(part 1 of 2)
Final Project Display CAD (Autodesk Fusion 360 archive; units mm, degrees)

design "Display Mechanism" references "STEP214 DIGITAL SERVO ASSEMBLY", "M4x2.2mm Hex Nut"
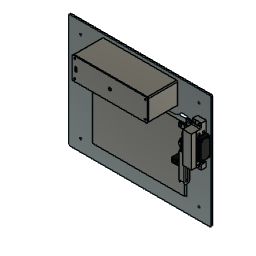
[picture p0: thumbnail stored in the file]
parameter "CaseWidth" = 190.24
parameter "CaseHeight" = 131.19
parameter "CaseThickness" = 9.525 (= "( 0.125 * 3 ) * 1 in")
parameter "FrameOffsetFromCase" = 2 comment "each side"
parameter "FrameSize" = 50 comment "width of each side"
parameter "HoleCenterFromTop" = 10 comment "pin hole in case distance to the center of the hole from the top of the csae"
parameter "PinDiameter" = 5
parameter "PinTolerance" = 1
parameter "PinDistanceIntoCase" = 10
parameter "PinEndTolerance" = 1 comment "distance between the end of the pin and the end of the pinhole in the case"
parameter "ServoArmFitTolerance" = 0.25
parameter "CaseAttachmentCircleTolerance" = 0.3
parameter "HexNutOffset" = -0.435 (= "2.54 mm - 3.475 mm + 0.5 mm") comment "hex nut hole offset in case attachment"
parameter "CaseAttachmentTolerance" = 0.3 comment "each side of the u-shape's offset from the case"
parameter "ServoMountSidesOffset" = 0.5
parameter "ServoMountScrewholePlaneOffset" = 1 comment "the plane perpendicular to the screws' offset from the plane with the screws"
parameter "PinHoleTolerance" = 0.2 comment "Tolerance on each side of the cylindrical pin"
parameter "HingeFrameCaseTolerance" = 0.2
sketch "Sketch1" plane through (0, 0, 0) normal (0, 1, 0) x axis (1, 0, 0)
  line L1 (-95.12, -65.595) -> (95.12, -65.595)
  line L2 (-95.12, 65.595) -> (-95.12, -65.595)
  line L3 (95.12, 65.595) -> (-95.12, 65.595)
  line L4 (95.12, -65.595) -> (95.12, 65.595)
  line L5 (-95.12, 65.595) -> (95.12, -65.595)
  line L6 (95.12, 65.595) -> (-95.12, -65.595)
  point P6 (0, 0)
  point P1 (0, 0)
  point P2 (95.12, -65.595)
  point P5 (95.12, 65.595)
  point P4 (-95.12, 65.595)
  horizontal L1
  perpendicular L1 L2
  parallel L1 L3
  parallel L2 L4
  coincident L5 P6
  coincident L6 P6
  coincident P1 P6
  dimension "d3" distance P2 P5 = 131.19 (= "CaseHeight")
  dimension "d4" distance P4 P5 = 190.24 (= "CaseWidth")
extrude "Extrude1" new body sketch "Sketch1" profile of L1 L2 L3 L4 along normal blind 9.525 (= "CaseThickness")
sketch "Sketch2" plane through (0, 0, 0) normal (0, -1, 0) x axis (1, 0, 0)
  line L1 (95.12, -65.595) -> (-95.12, -65.595)
  line L2 (95.12, 65.595) -> (95.12, -65.595)
  line L3 (-95.12, 65.595) -> (95.12, 65.595)
  line L4 (-95.12, -65.595) -> (-95.12, 65.595)
  line L5 (97.12, -67.595) -> (-97.12, -67.595)
  line L6 (97.12, 67.595) -> (97.12, -67.595)
  line L7 (-97.12, 67.595) -> (97.12, 67.595)
  line L8 (-97.12, -67.595) -> (-97.12, 67.595)
  line L9 (147.12, -117.595) -> (-147.12, -117.595)
  line L10 (147.12, 117.595) -> (147.12, -117.595)
  line L11 (-147.12, 117.595) -> (147.12, 117.595)
  line L12 (-147.12, -117.595) -> (-147.12, 117.595)
  dimension "d10" = 2 (= "FrameOffsetFromCase")
  dimension "d11" = 52 (= "FrameOffsetFromCase + FrameSize")
extrude "Extrude2" new body sketch "Sketch2" profile of L6 L5 L7 L8 L10 L9 L11 L12 no distance stored bodies "Frame"
sphere_primitive "SpherePrimitive1" Diameter 30
move_face "MoveFace1"
move "Move1"
work_plane "WorkPlane1" AlongDistance 8
split "Split1"
remove_body "RemoveBody1"
mirror "Mirror1" mirrorStitchTolerance 0.1
mirror "Mirror2" mirrorStitchTolerance 0.1
combine "Combine1"
sketch "Sketch4" plane through (95.12, 0, 0) normal (1, 0, 0) x axis (0, 1, 0)
  line L1 (0, -65.595) -> (0, 65.595)
  line L2 (9.525, -65.595) -> (0, -65.595)
  line L3 (9.525, 65.595) -> (9.525, -65.595)
  line L4 (0, 65.595) -> (9.525, 65.595)
  line L5 (4.7625, 55.595) -> (4.7625, 65.595)
  circle C1 centre (4.7625, 55.595) radius 3
  point P6 (4.7625, 65.595)
  point P7 (4.7625, 55.595)
  point P8 (4.7625, 55.595)
  midpoint L4 P6
  perpendicular L4 L5
  coincident P7 P8
  dimension "d21" distance P6 P7 = 10
  dimension "d24" diameter C1 = 6 (= "PinDiameter + PinTolerance")
extrude "Extrude3" cut sketch "Sketch4" profile of C1 no distance stored
sketch "Sketch5" plane through (97.12, 0, 0) normal (-1, 0, 0) x axis (0, -1, 0)
  line L1 (0, 67.595) -> (0, -67.595)
  line L2 (-9.525, 67.595) -> (0, 67.595)
  line L3 (-9.525, -67.595) -> (-9.525, 67.595)
  line L4 (0, -67.595) -> (-9.525, -67.595)
  circle C1 centre (-4.7625, 55.595) radius 3
  circle C2 centre (-4.7625, 55.595) radius 2.5
  concentric C1 C2
  dimension "d29" diameter C2 = 5 (= "PinDiameter")
extrude "Extrude4" add sketch "Sketch5" profile of C2 along normal blind 12 (= "FrameOffsetFromCase + PinDistanceIntoCase")
fillet "Fillet1" radius 3
mirror "Mirror3" mirrorStitchTolerance 0.1
sketch "Sketch6" plane through (0, 0, 0) normal (0, -1, 0) x axis (1, 0, 0)
  line L1 (-97.12, 52.8439) -> (-97.12, -67.595)
  line L2 (97.12, 67.595) -> (-97.12, 67.595)
  line L3 (97.12, 58.3461) -> (97.12, 67.595)
  curve K1 (97.12, 58.3461) -> (97.12, 52.8439)
  line L4 (97.12, -67.595) -> (97.12, 52.8439)
  line L5 (-97.12, -67.595) -> (97.12, -67.595)
  line L6 (-147.12, -117.595) -> (-147.12, 117.595)
  line L7 (147.12, -117.595) -> (-147.12, -117.595)
  line L8 (147.12, 117.595) -> (147.12, -117.595)
  line L9 (-147.12, 117.595) -> (147.12, 117.595)
  line L10 (140.0818, 50) -> (110, 50)
  line L11 (140.0818, 32.2031) -> (140.0818, 50)
  line L12 (110, 32.2031) -> (140.0818, 32.2031)
  line L13 (110, 50) -> (110, 32.2031)
  curve K2 (-97.12, 52.8439) -> (-97.12, 58.3461)
  line L14 (-97.12, 67.595) -> (-97.12, 58.3461)
  horizontal L10
  vertical L11
  horizontal L12
  vertical L13
extrude "Extrude5" new body sketch "Sketch6" profile of L10 L11 L12 L13 along normal blind 30 bodies "Servo"
sketch "Sketch7" plane through (0, 0, 0) normal (0, -1, 0) x axis (1, 0, 0)
  line L1 (95.12, -65.595) -> (-95.12, -65.595)
  line L2 (95.12, 65.595) -> (95.12, -65.595)
  line L3 (-95.12, 65.595) -> (95.12, 65.595)
  line L4 (-95.12, -65.595) -> (-95.12, 65.595)
  line L5 (89, 7.3258) -> (95.12, 7.3258)
  line L6 (89, 1) -> (89, 7.3258)
  line L7 (95.12, 1) -> (89, 1)
  line L8 (95.12, 7.3258) -> (95.12, 1)
  point P6 (95.12, 7.3258)
  horizontal L5
  vertical L6
  horizontal L7
  vertical L8
  coincident L2 P6
sketch "Sketch8" plane through (110, 0, 0) normal (-1, 0, 0) x axis (0, -1, 0)
  line L1 (0, 32.2031) -> (0, 50)
  line L2 (30, 32.2031) -> (0, 32.2031)
  line L3 (30, 50) -> (30, 32.2031)
  line L4 (0, 50) -> (30, 50)
  line L5 (0, 41.1016) -> (30, 41.1016)
  circle C1 centre (5.9888, 41.1016) radius 2.8985
  point P6 (30, 41.1016)
  point P7 (0, 41.1016)
  point P8 (5.9888, 41.1016)
  midpoint L3 P6
  midpoint L1 P7
  coincident L5 P8
extrude "Extrude6" add sketch "Sketch8" profile of C1 along normal blind 5
extrude "Extrude7" add sketch "Sketch7" profile of L2 L5 L6 L7 L8 along normal blind 20
sketch "Sketch9" plane through (95.12, 0, 0) normal (1, 0, 0) x axis (0, 1, 0)
  line L1 (0, -65.595) -> (0, 1)
  line L2 (9.525, -65.595) -> (0, -65.595)
  line L3 (9.525, 65.595) -> (9.525, -65.595)
  line L4 (0, 65.595) -> (9.525, 65.595)
  line L5 (0, 7.3258) -> (0, 65.595)
  line L6 (-20, 7.3258) -> (0, 7.3258)
  line L7 (-20, 1) -> (-20, 7.3258)
  line L8 (0, 1) -> (-20, 1)
  line L9 (-20, 7.3258) -> (0, 7.3258)
  line L10 (-20, 7.3258) -> (-20, 1)
  line L11 (-20, 1) -> (0, 1)
  line L12 (-1.5907, 4.1629) -> (-20, 4.1629)
  circle C1 centre (4.7625, 55.595) radius 3
  circle C2 centre (-7.1563, 4.1629) radius 2
  point P16 (-20, 4.1629)
  point P11 (-7.1563, 4.1629)
  midpoint L10 P16
  coincident P11 L12
  horizontal L12
extrude "Extrude8" add sketch "Sketch9" profile of C2 along normal blind 14
fillet "Fillet2" radius 5
sketch "Sketch10" plane through (105, 0, 0) normal (-1, 0, 0) x axis (0, -1, 0)
  line L1 (5.1563, 41) -> (5.1563, 4.1629)
  line L2 (9.1563, 41) -> (5.1563, 41)
  line L3 (9.1563, 4.1629) -> (9.1563, 41)
  line L4 (5.1563, -6.9539) -> (5.1563, 4.1629)
  line L5 (9.1563, -6.9539) -> (9.1563, 4.1629)
  line L6 (10.1563, -6.9539) -> (10.1563, 4.1629)
  line L7 (4.1563, -6.9539) -> (4.1563, 4.1629)
  line L8 (4.1563, 42) -> (4.1563, 4.1629)
  line L9 (10.1563, 42) -> (4.1563, 42)
  line L10 (10.1563, 4.1629) -> (10.1563, 42)
  circle C1 centre (5.9888, 41.1016) radius 2.8985
  circle C2 centre (7.1563, 4.1629) radius 2
  arc A1 centre (7.1563, 4.1629) radius 2 clockwise from (9.1563, 4.1629) to (5.1563, 4.1629)
  arc A2 centre (7.1563, -6.9539) radius 2 clockwise from (9.1563, -6.9539) to (5.1563, -6.9539)
  arc A3 centre (7.1563, -6.9539) radius 3 clockwise from (10.1563, -6.9539) to (4.1563, -6.9539)
  point P4 (5.1563, 4.1629)
  point P7 (9.1563, 4.1629)
  coincident C2 P4
  tangent C2 L1
  vertical L1
  perpendicular L1 L2
  coincident C2 P7
  tangent C2 L3
  perpendicular L2 L3
  tangent L3 A1
  tangent C2 L4
  tangent A1 L5
  tangent L5 A2
  tangent L4 A2
  dimension "d49" = -1
extrude "Extrude9" new body sketch "Sketch10" profile of C1 L1 L2 L3 L4 L5 A2 L6 L10 L7 A3 L8 L9 along normal blind 1
sketch "Sketch11" plane through (104, 0, 0) normal (-1, 0, 0) x axis (0, -1, 0)
  line L1 (5.1563, 41) -> (5.1563, -6.9539)
  line L2 (9.1563, 41) -> (5.1563, 41)
  line L3 (9.1563, -6.9539) -> (9.1563, 41)
  line L4 (4.1563, -6.9539) -> (4.1563, 42)
  line L5 (10.1563, 42) -> (10.1563, -6.9539)
  line L6 (4.1563, 42) -> (10.1563, 42)
  line L7 (9.1563, 33) -> (5.1563, 33)
  arc A1 centre (7.1563, -6.9539) radius 2 clockwise from (9.1563, -6.9539) to (5.1563, -6.9539)
  arc A2 centre (7.1563, -6.9539) radius 3 clockwise from (10.1563, -6.9539) to (4.1563, -6.9539)
  circle C1 centre (7.1563, 38.8292) radius 1.5
  circle C2 centre (7.1563, 34.8292) radius 1.5
  point P13 (5.1563, 33)
  point P14 (9.1563, 33)
  point P11 (7.1563, 38.8292)
  point P12 (7.1563, 34.8292)
  point P3 (5.1563, 41)
  point P4 (9.1563, 41)
  coincident L1 P13
  coincident L3 P14
  perpendicular L3 L7
  dimension "d50" diameter C1 = 3
  dimension "d51" diameter C2 = 3
  dimension "d52" distance P11 P12 = 4
  dimension "d198" distance P3 P4 = 4
  dimension "d199" distance L3 P11 = 2 (= "d198 / 2")
  dimension "d200" distance L3 P12 = 2 (= "d199")
extrude "Extrude10" new body sketch "Sketch11" profile of L1 L2 L3 C1 C2 L7 against normal blind 1
combine "Combine2"
extrude "Extrude11" new body of existing geometry blind 4
combine "Combine3"
component_from_bodies "Body->Comp1"
component_insert "Component Insert1"
move "Move1"
extrude "Extrude1" add of existing geometry blind 4
extrude "Extrude2" add of existing geometry blind 3
extrude "Extrude3" add of existing geometry blind 3
offset_faces "OffsetFaces1" distance 3
extrude "Extrude4" add of existing geometry blind 5
extrude "Extrude5" add of existing geometry blind 5
combine "Combine1" bodies "Servo Arm Attachment (1)", "Servo Arm Attachment (2)", "Servo Arm Attachment (3)", "Servo Arm Attachment (4)", "Servo Arm Attachment (5)", "Servo Arm Attachment (6)", "Servo Arm Attachment (7)", "Servo Arm Attachment (8)"
offset_faces "OffsetFaces2"
sketch "Sketch1" plane through (0, 0, 27.5) normal (0, 0, 1) x axis (-1, 0, 0)
  line L1 (-100, 13.6) -> (-100.45, 14.05)
  line L2 (-100, 16.0063) -> (-100, 13.6)
  line L3 (-110, 16.0063) -> (-100, 16.0063)
  line L4 (-110, 4.0063) -> (-110, 16.0063)
  line L5 (-100, 4.0063) -> (-110, 4.0063)
  line L6 (-100, 6.4) -> (-100, 4.0063)
  line L7 (-100.45, 5.95) -> (-100, 6.4)
  line L8 (-103.9036, 5.95) -> (-100.45, 5.95)
  line L9 (-104.25, 6.2964) -> (-103.9036, 5.95)
  line L10 (-104.25, 13.7036) -> (-104.25, 6.2964)
  line L11 (-103.9036, 14.05) -> (-104.25, 13.7036)
  line L12 (-100.45, 14.05) -> (-103.9036, 14.05)
  line L13 (-100, 14.05) -> (-100.45, 14.05)
  point P2 (-100.45, 14.05)
  point P14 (-100.45, 14.05)
  point P15 (-100, 14.05)
  coincident P2 P14
  coincident L2 P15
  perpendicular L2 L13
sweep "Sweep1" sketch "Sketch1" TwistAngle 0 TaperAngle 0
extrude "Extrude12" cut of existing geometry blind -2.833
sketch "Sketch13" plane through (0, 0, 7.3258) normal (0, 0, 1) x axis (-1, 0, 0)
  line L1 (-95.12, 17.167) -> (-89, 17.167)
  line L2 (-95.12, 13.401) -> (-95.12, 17.167)
  curve K1 (-95.12, 13.401) -> (-95.12, 0.9116)
  line L3 (-95.12, 0) -> (-95.12, 0.9116)
  line L4 (-89, 0) -> (-95.12, 0)
  line L5 (-89, 17.167) -> (-89, 0)
  line L6 (-112, 0) -> (-95.12, 0)
  line L7 (-112, 18) -> (-112, 0)
  line L8 (-95.12, 18) -> (-112, 18)
  line L9 (-95.12, 0) -> (-95.12, 18)
  point P6 (-95.12, 0)
  point P8 (-95.12, 0)
  horizontal L6
  vertical L7
  horizontal L8
  vertical L9
  coincident P6 P8
extrude "Extrude13" cut sketch "Sketch13" profile of L2 K1 L3 L6 L7 L8 L9 against normal blind 6.326
fillet "Fillet3" radius 2
sketch "Sketch14" plane through (95.12, 0, 0) normal (1, 0, 0) x axis (0, 1, 0)
  line L1 (0, -65.595) -> (0, -1)
  line L2 (9.525, -65.595) -> (0, -65.595)
  line L3 (9.525, 65.595) -> (9.525, -65.595)
  line L4 (0, 65.595) -> (9.525, 65.595)
  line L5 (0, 9.3258) -> (0, 65.595)
  line L6 (-17.167, 7.3258) -> (-2, 7.3258)
  line L7 (-17.167, 1) -> (-17.167, 7.3258)
  line L8 (-2, 1) -> (-17.167, 1)
  line L9 (-12.0063, 9.5) -> (-12.0063, -25.4539)
  line L10 (-8.0063, -25.4539) -> (-8.0063, 9.5)
  line L11 (-8.0063, 9.5) -> (-12.0063, 9.5)
  line L12 (-10.0063, 1.6266) -> (-10.0063, 9.5)
  line L13 (-12.3112, 1) -> (-12.3112, 7.3258)
  line L14 (-9.7419, 4.1629) -> (-12.3112, 4.1629)
  arc A1 centre (-2, 9.3258) radius 2 clockwise from (0, 9.3258) to (-2, 7.3258)
  arc A2 centre (-2, -1) radius 2 clockwise from (-2, 1) to (0, -1)
  circle C1 centre (4.7625, 55.595) radius 3
  circle C2 centre (-11.0265, 4.1629) radius 3.0202
  circle C3 centre (-11.0265, 4.1629) radius 2.7202
  point P19 (-10.0063, 9.5)
  point P21 (-12.3112, 7.3258)
  point P22 (-12.3112, 1)
  point P23 (-12.3112, 4.1629)
  point P25 (-11.0265, 4.1629)
  midpoint L11 P19
  perpendicular L11 L12
  coincident L6 P21
  coincident L8 P22
  perpendicular L8 L13
  midpoint L13 P23
  perpendicular L12 L14
  midpoint L14 P25
  tangent L10 C2
extrude "Extrude14" add sketch "Sketch14" profile of C3 along normal blind 14.88
extrude "Extrude15" add of existing geometry blind 5
split "Split2" bodies "Case Attachment"
position "Position1"
sketch "Sketch15" plane through (0, 9.525, 0) normal (0, 1, 0) x axis (-1, 0, 0)
  line L1 (95.12, -65.595) -> (-95.12, -65.595)
  line L2 (95.12, 65.595) -> (95.12, -65.595)
  line L3 (-95.12, 65.595) -> (95.12, 65.595)
  line L4 (-95.12, -65.595) -> (-95.12, 65.595)
  line L5 (-87, -1) -> (-87, 9.3258)
  line L6 (-87, 9.3258) -> (-95.12, 9.3258)
  line L7 (-95.12, -1) -> (-87, -1)
extrude "Extrude16" add sketch "Sketch15" profile of L4 L5 L6 L7 along normal blind 5
sketch "Sketch16" plane through (95.12, 0, 0) normal (1, 0, 0) x axis (0, 1, 0)
  line L1 (0, -65.595) -> (0, 65.595)
  line L2 (9.525, -65.595) -> (0, -65.595)
  line L3 (9.525, -1) -> (9.525, -65.595)
  line L4 (14.525, -1) -> (9.525, -1)
  line L5 (14.525, 9.3258) -> (14.525, -1)
  line L6 (9.525, 9.3258) -> (14.525, 9.3258)
  line L7 (9.525, 65.595) -> (9.525, 9.3258)
  line L8 (0, 65.595) -> (9.525, 65.595)
  line L9 (0, 9.3258) -> (14.525, 9.3258)
  line L10 (0, -1) -> (14.525, -1)
  circle C1 centre (4.7625, 55.595) radius 3
  point P8 (14.525, 9.3258)
  point P11 (14.525, 9.3258)
  point P12 (0, 9.3258)
  point P7 (14.525, -1)
  point P13 (14.525, -1)
  point P14 (0, -1)
  coincident P8 P11
  coincident L1 P12
  perpendicular L1 L9
  coincident P7 P13
  coincident L1 P14
  perpendicular L1 L10
extrude "Extrude17" add sketch "Sketch16" profile of L1 L4 L5 L6 L9 L10 along normal blind 1.5 bodies "Case Attachment"
split "Split3" bodies "Case Attachment"
split "Split4" bodies "Case (2)"
work_plane "WorkPlane2" AlongDistance 0
split "Split5" bodies "Case (3)"
work_plane "WorkPlane3" RotateAngle 90
split "Split6" bodies "Case (2) (1)"
move "Move2"
combine "Combine4" bodies "Case (2)"
extrude "Extrude18" new body of existing geometry blind 2
extrude "Extrude19" new body of existing geometry blind 2
combine "Combine5" bodies "Case (2) (1)", "Case (3)"
fillet "Fillet5" radius 3
sketch "Sketch17" plane through (0, 14.525, 0) normal (0, 1, 0) x axis (-1, 0, 0)
  line L1 (-87, -1) -> (-96.62, -1)
  line L2 (-87, 9.3258) -> (-87, -1)
  line L3 (-96.62, 9.3258) -> (-87, 9.3258)
  line L4 (-96.62, -1) -> (-96.62, 9.3258)
  line L5 (-87, -1) -> (-96.62, 9.3258)
  line L6 (-96.62, -1) -> (-87, 9.3258)
  circle C1 centre (-91.81, 4.1629) radius 2
  point P3 (-87, -1)
  point P6 (-87, -1)
  point P4 (-87, 9.3258)
  point P7 (-87, 9.3258)
  point P8 (-96.62, -1)
  point P9 (-91.81, 4.1629)
  point P5 (-96.62, 9.3258)
  point P10 (-96.62, 9.3258)
  coincident P3 P6
  coincident P4 P7
  coincident L1 P8
  midpoint L6 P9
  coincident P5 P10
  dimension "d102" diameter C1 = 4
extrude "Extrude20" cut sketch "Sketch17" profile of C1 against normal blind 31.692
component_from_bodies "Body->Comp2"
sketch "Sketch1" plane through (0, 14.525, 0) normal (0, 1, 0) x axis (-1, 0, 0)
  line L1 (-87, -1) -> (-96.62, -1)
  line L2 (-87, 9.3258) -> (-87, -1)
  line L3 (-96.62, 9.3258) -> (-87, 9.3258)
  line L4 (-96.62, -1) -> (-96.62, 9.3258)
  line L5 (-95.31, 7.6629) -> (-88.31, 7.6629)
  line L6 (-95.31, 0.6629) -> (-95.31, 7.6629)
  line L7 (-88.31, 0.6629) -> (-95.31, 0.6629)
  line L8 (-88.31, 7.6629) -> (-88.31, 0.6629)
  line L9 (-95.31, 0.6629) -> (-88.31, 7.6629)
  line L10 (-88.31, 0.6629) -> (-95.31, 7.6629)
  circle C1 centre (-91.81, 4.1629) radius 2
  point P11 (-91.81, 4.1629)
  point P2 (-91.81, 4.1629)
  point P9 (-95.31, 0.6629)
  point P10 (-88.31, 0.6629)
  point P8 (-95.31, 7.6629)
  horizontal L5
  perpendicular L5 L6
  parallel L5 L7
  parallel L6 L8
  coincident L9 P11
  coincident L10 P11
  coincident P2 P11
  dimension "d105" distance P9 P10 = 7
  dimension "d106" distance P8 P9 = 7
extrude "Extrude1" cut sketch "Sketch1" profile of C1 L5 L6 L7 L8 against normal blind 3
component_insert "Component Insert1"
position "Position2"
sketch "Sketch2" plane through (0, -17.167, 0) normal (0, -1, 0) x axis (1, 0, 0)
  line L1 (95.12, 7.3258) -> (95.12, 1)
  line L2 (89, 7.3258) -> (95.12, 7.3258)
  line L3 (89, 1) -> (89, 7.3258)
  line L4 (95.12, 1) -> (89, 1)
  line L5 (87.31, 8.6629) -> (96.31, 8.6629)
  line L6 (87.31, -0.3371) -> (87.31, 8.6629)
  line L7 (96.31, -0.3371) -> (87.31, -0.3371)
  line L8 (96.31, 8.6629) -> (96.31, -0.3371)
  line L9 (87.31, -0.3371) -> (96.31, 8.6629)
  line L10 (96.31, -0.3371) -> (87.31, 8.6629)
  line L11 (89.7694, 7.6375) -> (93.8109, 7.6375)
  line L12 (87.7487, 4.1375) -> (89.7694, 7.6375)
  line L13 (89.7694, 0.6375) -> (87.7487, 4.1375)
  line L14 (93.8109, 0.6375) -> (89.7694, 0.6375)
  line L15 (95.8316, 4.1375) -> (93.8109, 0.6375)
  line L16 (93.8109, 7.6375) -> (95.8316, 4.1375)
  line L17 (88.2998, 4.1402) -> (90.0353, 7.1915)
  line L18 (90.0745, 1.1116) -> (88.2998, 4.1402)
  line L19 (93.5847, 1.1343) -> (90.0745, 1.1116)
  line L20 (95.3202, 4.1856) -> (93.5847, 1.1343)
  line L21 (93.5455, 7.2142) -> (95.3202, 4.1856)
  line L22 (90.0353, 7.1915) -> (93.5455, 7.2142)
  circle C1 centre (91.81, 4.1629) radius 2
  point P11 (91.81, 4.1629)
  point P2 (91.81, 4.1629)
  point P30 (91.81, 4.1629)
  point P9 (87.31, -0.3371)
  point P10 (96.31, -0.3371)
  point P8 (87.31, 8.6629)
  horizontal L5
  perpendicular L5 L6
  parallel L5 L7
  parallel L6 L8
  coincident L9 P11
  coincident L10 P11
  coincident P2 P11
  coincident P11 P30
  dimension "d109" distance P9 P10 = 9
  dimension "d110" distance P8 P9 = 9
  dimension "d112" distance P30 L22 = 3.04 (= "3.475 mm + HexNutOffset")
extrude "Extrude2" cut sketch "Sketch2" profile of C1 L1 L2 L3 L4 L11 L12 L13 L14 L15 L16 L17 L18 L19 L20 L21 L22 against normal blind 15.5
extrude "Extrude3" add sketch "Sketch2" profile of L1 L2 L3 L4 L5 L6 L7 L8 L17 L18 L19 L20 L21 L22 against normal blind 17
fillet "Fillet1" radius 1
fillet "Fillet2" radius 1
fillet "Fillet3" radius 3
position "Position3"
sketch "Sketch3" plane through (0, -17.167, 0) normal (0, -1, 0) x axis (1, 0, 0)
  line L1 (96.31, 8.6629) -> (96.31, -0.3371)
  line L2 (87.31, 8.6629) -> (96.31, 8.6629)
  line L3 (87.31, -0.3371) -> (87.31, 8.6629)
  line L4 (96.31, -0.3371) -> (87.31, -0.3371)
  line L5 (93.5847, 1.1343) -> (95.3202, 4.1856)
  line L6 (90.0745, 1.1116) -> (93.5847, 1.1343)
  line L7 (88.2998, 4.1402) -> (90.0745, 1.1116)
  line L8 (90.0353, 7.1915) -> (88.2998, 4.1402)
  line L9 (93.5455, 7.2142) -> (90.0353, 7.1915)
  line L10 (95.3202, 4.1856) -> (93.5455, 7.2142)
  line L11 (97.5, 10.5) -> (85, 10.5)
  line L12 (97.5, -3) -> (97.5, 10.5)
  line L13 (85, -3) -> (97.5, -3)
  line L14 (85, 10.5) -> (85, -3)
  horizontal L11
  vertical L12
  horizontal L13
  vertical L14
extrude "Extrude4" cut sketch "Sketch3" profile of L1 L2 L3 L4 L11 L12 L13 L14 against normal blind 15.513 bodies "Case Attachment (1)"
extrude "Extrude5" add of existing geometry blind 0.31
extrude "Extrude6" add of existing geometry blind 0.31
extrude "Extrude7" add of existing geometry blind 1
sketch "Sketch4" plane through (96.62, 0, 0) normal (1, 0, 0) x axis (0, 1, 0)
  line L1 (-1.654, 8.6629) -> (-1.654, 9.3258)
  line L2 (-17.167, 8.6629) -> (-1.654, 8.6629)
  line L3 (-17.167, -0.3371) -> (-17.167, 8.6629)
  line L4 (-1.654, -0.3371) -> (-17.167, -0.3371)
  line L5 (-1.654, -1) -> (-1.654, -0.3371)
  line L6 (14.525, -1) -> (-1.654, -1)
  line L7 (14.525, 9.3258) -> (14.525, -1)
  line L8 (-1.654, 9.3258) -> (14.525, 9.3258)
  line L9 (-1.654, -0.3371) -> (-1.654, 8.6629)
  point P3 (-1.654, 8.6629)
  point P10 (-1.654, 8.6629)
  point P6 (-1.654, -0.3371)
  point P11 (-1.654, -0.3371)
  coincident P3 P10
  coincident P6 P11
extrude "Extrude8" add sketch "Sketch4" profile of L2 L3 L4 L9 along normal blind 0.88 bodies "Case Attachment (1)"
fillet "Fillet4" radius 1
fillet "Fillet5" radius 0.1
fillet "Fillet6" radius 1
fillet "Fillet7" radius 1
sketch "Sketch18" plane through (0, 0, 0) normal (0, -1, 0) x axis (1, 0, 0)
  line L1 (95.12, 65.595) -> (95.12, -65.595)
  line L2 (-95.12, 65.595) -> (95.12, 65.595)
  line L3 (-95.12, -65.595) -> (-95.12, 65.595)
  line L4 (95.12, -65.595) -> (-95.12, -65.595)
  line L5 (95.12, 4.2278) -> (91.8082, 4.2278)
  line L6 (91.8082, 65.595) -> (91.8082, 4.2278)
  circle C1 centre (91.8082, 4.2278) radius 2
  circle C2 centre (91.8082, 4.2278) radius 3.3118
  point P7 (91.8082, 4.2278)
  point P8 (91.8082, 4.2278)
  point P9 (95.12, 4.2278)
  point P10 (91.8082, 4.2278)
  point P11 (91.8082, 65.595)
  concentric C1 C2
  tangent L1 C2
  coincident P7 P8
  coincident L1 P9
  perpendicular L1 L5
  coincident P7 P10
  coincident L2 P11
  perpendicular L2 L6
  dimension "d141" distance P10 P11 = 61.3672
  dimension "d142" distance P8 P9 = 3.3118
offset_faces "OffsetFaces1"
offset_faces "OffsetFaces2"
offset_faces "OffsetFaces3"
remove_body "RemoveBody4"
sketch "Sketch19" plane through (0, 0, 0) normal (0, -1, 0) x axis (1, 0, 0)
  line L1 (-97.12, 52.8439) -> (-97.12, -67.595)
  curve K1 (-97.12, 52.8439) -> (-97.12, 58.3461)
  line L2 (-97.12, 67.595) -> (-97.12, 58.3461)
  line L3 (97.12, 67.595) -> (-97.12, 67.595)
  line L4 (97.12, 58.3461) -> (97.12, 67.595)
  curve K2 (97.12, 58.3461) -> (97.12, 52.8439)
  line L5 (97.12, -67.595) -> (97.12, 52.8439)
  line L6 (-97.12, -67.595) -> (97.12, -67.595)
  line L7 (-147.12, -117.595) -> (-147.12, 117.595)
  line L8 (147.12, -117.595) -> (-147.12, -117.595)
  line L9 (147.12, 117.595) -> (147.12, -117.595)
  line L10 (-147.12, 117.595) -> (147.12, 117.595)
  line L11 (121, 71.2) -> (141, 71.2)
  line L12 (121, 83.2) -> (121, 71.2)
  line L13 (141, 83.2) -> (121, 83.2)
  line L14 (141, 71.2) -> (141, 83.2)
  line L15 (121, 30.8214) -> (141.0001, 30.8214)
  line L16 (121, 18.8214) -> (121, 30.8214)
  line L17 (141.0001, 18.8214) -> (121, 18.8214)
  line L18 (141.0001, 30.8214) -> (141.0001, 18.8214)
  line L19 (141, 83.2) -> (121, 83.2)
  line L20 (121, 18.8214) -> (141.0001, 18.8214)
  line L21 (141.0001, 30.3214) -> (141.0001, 18.8214)
  line L22 (121, 30.3214) -> (141.0001, 30.3214)
  line L23 (121, 30.3214) -> (121, 18.8214)
  line L24 (141, 71.7) -> (141, 83.2)
  line L25 (121, 71.7) -> (141, 71.7)
  line L26 (121, 71.7) -> (121, 83.2)
  line L27 (140.0001, 24.5714) -> (141.0001, 24.5714)
  line L28 (122, 24.8214) -> (121, 24.8214)
  line L29 (122, 18.8214) -> (122, 30.3214)
  line L30 (140.0001, 18.8214) -> (140.0001, 30.3214)
  line L31 (122, 79) -> (121, 79)
  line L32 (140, 78) -> (141, 78)
  line L33 (122, 71.7) -> (122, 83.2)
  line L34 (140, 71.7) -> (140, 83.2)
  point P22 (141.0001, 30.3214)
  point P23 (121, 30.3214)
  point P24 (141, 71.7)
  point P25 (121, 71.7)
  point P26 (141.0001, 24.5714)
  point P28 (121, 24.8214)
  point P30 (122, 30.3214)
  point P31 (122, 18.8214)
  point P32 (140.0001, 30.3214)
  point P33 (140.0001, 18.8214)
  point P34 (121, 79)
  point P36 (141, 78)
  point P38 (122, 83.2)
  point P39 (122, 71.7)
  point P40 (140, 83.2)
  point P41 (140, 71.7)
  point P37 (140, 78)
  point P35 (122, 79)
  point P27 (140.0001, 24.5714)
  point P29 (122, 24.8214)
  point P18 (141.0001, 30.8214)
  point P21 (141.0001, 18.8214)
  point P14 (141, 71.2)
  point P17 (141, 83.2)
  horizontal L11
  vertical L12
  horizontal L13
  vertical L14
  horizontal L15
  vertical L16
  horizontal L17
  vertical L18
  coincident L18 P22
  coincident L16 P23
  perpendicular L16 L22
  coincident L14 P24
  coincident L12 P25
  perpendicular L12 L25
  midpoint L21 P26
  perpendicular L18 L27
  midpoint L16 P28
  perpendicular L16 L28
  coincident L22 P30
  coincident L17 P31
  perpendicular L17 L29
  coincident L22 P32
  coincident L17 P33
  perpendicular L17 L30
  coincident L12 P34
  perpendicular L26 L31
  coincident L14 P36
  perpendicular L14 L32
  coincident L19 P38
  coincident L25 P39
  perpendicular L25 L33
  coincident L19 P40
  coincident L25 P41
  perpendicular L25 L34
  coincident P37 L34
  coincident P35 L33
  coincident P27 L30
  coincident P29 L29
  dimension "d147" distance P18 P21 = 12
  dimension "d148" distance P14 P17 = 12
  dimension "d150" distance P21 P22 = 11.5 (= "d147 - ServoMountSidesOffset")
  dimension "d151" distance P17 P24 = 11.5 (= "d148 - ServoMountSidesOffset")
  dimension "d153" distance P26 P27 = 1 (= "ServoMountScrewholePlaneOffset")
  dimension "d154" distance P28 P29 = 1 (= "d153")
  dimension "d155" distance P34 P35 = 1 (= "ServoMountScrewholePlaneOffset")
  dimension "d156" distance P36 P37 = 1 (= "ServoMountScrewholePlaneOffset")
extrude "Extrude21" add sketch "Sketch19" profile of L19 L20 L22 L25 L29 L30 L33 L34 to an object
extrude "Extrude22" add of existing geometry blind 0.5 (= "ServoMountSidesOffset")
sketch "Sketch20" plane through (0, -20.4985, 0) normal (0, -1, 0) x axis (1, 0, 0)
  line L1 (122, 83.2) -> (140, 83.2)
  line L2 (122, 71.7) -> (122, 83.2)
  line L3 (140, 71.7) -> (122, 71.7)
  line L4 (140, 83.2) -> (140, 71.7)
  line L5 (140.0001, 83.2) -> (122, 83.2)
  line L6 (140.0001, 18.8214) -> (140.0001, 83.2)
  line L7 (122, 18.8214) -> (140.0001, 18.8214)
  line L8 (122, 83.2) -> (122, 18.8214)
  point P3 (122, 83.2)
  point P6 (122, 83.2)
  point P10 (140.0001, 18.8214)
  horizontal L5
  vertical L6
  horizontal L7
  vertical L8
  coincident P3 P6
  coincident L6 P10
  coincident L7 P10
extrude "Extrude23" add sketch "Sketch20" along normal blind 10
sketch "Sketch21" plane through (0, 0, 0) normal (0, -1, 0) x axis (1, 0, 0)
  line L1 (122, 18.8214) -> (140.0001, 18.8214)
  line L2 (122, 30.3214) -> (122, 18.8214)
  line L3 (140.0001, 30.3214) -> (122, 30.3214)
  line L4 (140.0001, 18.8214) -> (140.0001, 30.3214)
  line L5 (122, 71.7) -> (140, 71.7)
  line L6 (122, 83.2) -> (122, 71.7)
  line L7 (140, 83.2) -> (122, 83.2)
  line L8 (-97.12, 52.8439) -> (-97.12, -67.595)
  curve K1 (-97.12, 52.8439) -> (-97.12, 58.3461)
  line L9 (-97.12, 67.595) -> (-97.12, 58.3461)
  line L10 (97.12, 67.595) -> (-97.12, 67.595)
  line L11 (97.12, 58.3461) -> (97.12, 67.595)
  curve K2 (97.12, 58.3461) -> (97.12, 52.8439)
  line L12 (97.12, -67.595) -> (97.12, 52.8439)
  line L13 (-97.12, -67.595) -> (97.12, -67.595)
  line L14 (-147.12, -117.595) -> (-147.12, 117.595)
  line L15 (147.12, -117.595) -> (-147.12, -117.595)
  line L16 (147.12, 117.595) -> (147.12, -117.595)
  line L17 (-147.12, 117.595) -> (147.12, 117.595)
  line L18 (122, 83.2) -> (140, 83.2)
  line L19 (122, 93) -> (122, 83.2)
  line L20 (140, 93) -> (122, 93)
  line L21 (140, 83.2) -> (140, 93)
  line L22 (140, 18.8214) -> (122, 18.8214)
  line L23 (140, 8.8214) -> (140, 18.8214)
  line L24 (122, 8.8214) -> (140, 8.8214)
  line L25 (122, 18.8214) -> (122, 8.8214)
  line L26 (140, 71.7) -> (140, 83.2)
  point P9 (140, 83.2)
  point P22 (140, 83.2)
  point P3 (122, 18.8214)
  point P26 (122, 18.8214)
  point P29 (122, 8.8214)
  horizontal L18
  vertical L19
  horizontal L20
  vertical L21
  coincident P9 P22
  horizontal L22
  vertical L23
  horizontal L24
  vertical L25
  coincident P3 P26
  dimension "d163" distance P26 P29 = 10
extrude "Extrude24" add sketch "Sketch21" profile of L1 L7 L18 L19 L20 L21 L22 L23 L24 L25 along normal blind 10
extrude "Extrude25" add of existing geometry blind 20
split "Split7" bodies "Frame (1)", "Frame (3)", "Frame (4)"
move "Move3"
combine "Combine6" bodies "Frame", "Frame (4)", "Frame (3)", "Frame (1)"
sketch "Sketch22" plane through (0, -10, 0) normal (0, -1, 0) x axis (1, 0, 0)
  line L1 (122, 93) -> (140, 93)
  line L2 (122, 83.2) -> (122, 93)
  line L3 (140, 83.2) -> (122, 83.2)
  line L4 (140, 93) -> (140, 83.2)
  circle C1 centre (126.5, 88.1) radius 2
  circle C2 centre (135.5, 88.1) radius 2
  point P6 (126.5, 88.1)
  point P7 (135.5, 88.1)
  point P4 (122, 83.2)
  point P5 (140, 83.2)
  dimension "d168" diameter C1 = 4
  dimension "d169" diameter C2 = 4
  dimension "d170" distance L1 L3 = 9.8
  dimension "d171" distance L1 P6 = 4.9 (= "d170 / 2")
  dimension "d172" distance L1 P7 = 4.9 (= "d171")
  dimension "d173" distance L2 P6 = 4.5 (= "d174 / 4")
  dimension "d174" distance P4 P5 = 18
  dimension "d175" distance L4 P7 = 4.5 (= "d173")
extrude "Extrude26" cut sketch "Sketch22" profile of C1 C2 against normal blind 19.525
work_plane "WorkPlane4"
mirror "Mirror4" mirrorStitchTolerance 0.1
sketch "Sketch23" plane through (122, 0, 0) normal (-1, 0, 0) x axis (0, -1, 0)
  line L1 (0, 71.7) -> (0, 93)
  line L2 (20.4985, 71.7) -> (0, 71.7)
  line L3 (20.4985, 30.3214) -> (20.4985, 71.7)
  line L4 (0, 30.3214) -> (20.4985, 30.3214)
  line L5 (0, 8.8214) -> (0, 30.3214)
  line L6 (10, 8.8214) -> (0, 8.8214)
  line L7 (10, 18.8214) -> (10, 8.8214)
  line L8 (30.4985, 18.8214) -> (10, 18.8214)
  line L9 (30.4985, 83.2) -> (30.4985, 18.8214)
  line L10 (10, 83.2) -> (30.4985, 83.2)
  line L11 (10, 93) -> (10, 83.2)
  line L12 (0, 93) -> (10, 93)
  arc A1 centre (14.9985, 26.8993) radius 2.25 clockwise from (13.9985, 24.8838) to (15.9985, 24.8838)
  arc A2 centre (4.9985, 26.8993) radius 2.25 clockwise from (3.9985, 24.8838) to (5.9985, 24.8838)
  arc A3 centre (4.9985, 74.8993) radius 2.25 clockwise from (5.9985, 76.9149) to (3.9985, 76.9149)
  arc A4 centre (14.9985, 74.8993) radius 2.25 clockwise from (15.9985, 76.9149) to (13.9985, 76.9149)
  circle C1 centre (14.9985, 74.8993) radius 2.25
  circle C2 centre (4.9985, 74.8993) radius 2.25
  circle C3 centre (4.9985, 26.8993) radius 2.25
  circle C4 centre (14.9985, 26.8993) radius 2.25
  concentric A4 C1
  concentric A3 C2
  concentric A2 C3
  concentric A1 C4
extrude "Extrude27" cut sketch "Sketch23" profile of A1 A2 A3 A4 C1 C2 C3 C4 against normal blind 80
sketch "Sketch24" plane through (140.0001, 0, 0) normal (1, 0, 0) x axis (0, 1, 0)
  line L1 (0, 18.8214) -> (-30.4985, 18.8214)
  line L2 (0, 30.3214) -> (0, 18.8214)
  line L3 (-20.4985, 30.3214) -> (0, 30.3214)
  line L4 (-20.4985, 83.2) -> (-20.4985, 30.3214)
  line L5 (-30.4985, 83.2) -> (-20.4985, 83.2)
  line L6 (-30.4985, 18.8214) -> (-30.4985, 83.2)
  line L7 (-20.4985, 18.8214) -> (-20.4985, 30.3214)
  circle C1 centre (-14.9985, 26.8993) radius 2.25
  circle C2 centre (-4.9985, 26.8993) radius 2.25
  point P7 (-20.4985, 30.3214)
  point P10 (-20.4985, 30.3214)
  coincident P7 P10
  perpendicular L3 L7
extrude "Extrude28" cut sketch "Sketch24" profile of C1 C2 L1 L2 L3 L7 against normal blind 3
fillet "Fillet6" radius 2
fillet "Fillet7" radius 3
fillet "Fillet8" radius 2
fillet "Fillet9" radius 1
fillet "Fillet10" radius 2
split "Split8" bodies "Servo Mount"
fillet "Fillet11" radius 1
sketch "Sketch25" plane through (0, 0, 0) normal (0, -1, 0) x axis (1, 0, 0)
  line L1 (-97.12, 52.8439) -> (-97.12, -67.595)
  curve K1 (-97.12, 52.8439) -> (-97.12, 58.3461)
  line L2 (-97.12, 67.595) -> (-97.12, 58.3461)
  line L3 (97.12, 67.595) -> (-97.12, 67.595)
  line L4 (97.12, 58.3461) -> (97.12, 67.595)
  curve K2 (97.12, 58.3461) -> (97.12, 52.8439)
  line L5 (97.12, -67.595) -> (97.12, 52.8439)
  line L6 (-97.12, -67.595) -> (97.12, -67.595)
  line L7 (-147.12, -117.595) -> (-147.12, 137.595)
  line L8 (147.12, -117.595) -> (-147.12, -117.595)
  line L9 (147.12, 137.595) -> (147.12, -117.595)
  line L10 (-147.12, 137.595) -> (147.12, 137.595)
  line L11 (-80, 65.0468) -> (-97.12, 65.0468)
  line L12 (-80, 47) -> (-80, 65.0468)
  line L13 (-97.12, 47) -> (-80, 47)
  line L14 (-97.12, 65.0468) -> (-97.12, 47)
  circle C1 centre (126.5, 13.9214) radius 2
  circle C2 centre (135.5, 13.9214) radius 2
  circle C3 centre (135.5, 88.1) radius 2
  circle C4 centre (126.5, 88.1) radius 2
  point P18 (-97.12, 65.0468)
  horizontal L11
  vertical L12
  horizontal L13
  vertical L14
  coincident L2 P18
extrude "Extrude29" cut sketch "Sketch25" profile of L1 K1 L2 L11 L12 L13 L14 against normal blind 55
extrude "Extrude30" add of existing geometry to an object
sketch "Sketch26" plane through (0, 0, 0) normal (0, -1, 0) x axis (1, 0, 0)
  line L1 (-97.12, 67.595) -> (-97.12, -67.595)
  line L2 (97.12, 67.595) -> (-97.12, 67.595)
  line L3 (97.12, 58.3461) -> (97.12, 67.595)
  curve K1 (97.12, 58.3461) -> (97.12, 52.8439)
  line L4 (97.12, -67.595) -> (97.12, 52.8439)
  line L5 (-97.12, -67.595) -> (97.12, -67.595)
  line L6 (-147.12, -117.595) -> (-147.12, 137.595)
  line L7 (147.12, -117.595) -> (-147.12, -117.595)
  line L8 (147.12, 137.595) -> (147.12, -117.595)
  line L9 (-147.12, 137.595) -> (147.12, 137.595)
  line L10 (81, 65.1951) -> (97.12, 65.1951)
  line L11 (81, 47) -> (81, 65.1951)
  line L12 (97.12, 47) -> (81, 47)
  line L13 (97.12, 65.1951) -> (97.12, 47)
  circle C1 centre (126.5, 13.9214) radius 2
  circle C2 centre (135.5, 13.9214) radius 2
  circle C3 centre (135.5, 88.1) radius 2
  circle C4 centre (126.5, 88.1) radius 2
  point P16 (97.12, 65.1951)
  horizontal L10
  vertical L11
  horizontal L12
  vertical L13
  coincident L3 P16
extrude "Extrude31" cut sketch "Sketch26" profile of L3 K1 L4 L10 L11 L12 L13 against normal blind 10
extrude "Extrude32" add of existing geometry to an object
sketch "Sketch27" plane through (0, 0, 0) normal (0, -1, 0) x axis (1, 0, 0)
  line L1 (95.12, 65.595) -> (95.12, -65.595)
  line L2 (-95.12, 65.595) -> (95.12, 65.595)
  line L3 (-95.12, -65.595) -> (-95.12, 65.595)
  line L4 (95.12, -65.595) -> (-95.12, -65.595)
  line L5 (-90.12, 65.595) -> (-95.12, 65.595)
  line L6 (-90.12, 60.595) -> (-90.12, 65.595)
  line L7 (-95.12, 60.595) -> (-90.12, 60.595)
  line L8 (-95.12, 65.595) -> (-95.12, 60.595)
  circle C1 centre (-90.12, 60.595) radius 2.25
  point P4 (-95.12, 65.595)
  point P6 (-95.12, 65.595)
  point P8 (-90.12, 60.595)
  point P10 (-90.12, 60.595)
  point P7 (-90.12, 65.595)
  point P9 (-95.12, 60.595)
  horizontal L5
  vertical L6
  horizontal L7
  vertical L8
  coincident P4 P6
  coincident P8 P10
  dimension "d209" distance P6 P7 = 5
  dimension "d210" distance P6 P9 = 5
  dimension "d211" diameter C1 = 4.5
extrude "Extrude33" cut sketch "Sketch27" profile of C1 against normal blind 10
sketch "Sketch28" plane through (0, 0, 0) normal (0, -1, 0) x axis (1, 0, 0)
  line L1 (-147.12, -117.595) -> (-147.12, 137.595)
  line L2 (147.12, -117.595) -> (-147.12, -117.595)
  line L3 (147.12, 137.595) -> (147.12, -117.595)
  line L4 (-147.12, 137.595) -> (147.12, 137.595)
  line L5 (97.12, -67.595) -> (97.12, 67.595)
  line L6 (-97.12, -67.595) -> (97.12, -67.595)
  line L7 (-97.12, 67.595) -> (-97.12, -67.595)
  line L8 (97.12, 67.595) -> (-97.12, 67.595)
  line L9 (-107.12, 67.595) -> (-97.12, 67.595)
  line L10 (-107.12, 53.595) -> (-107.12, 67.595)
  line L11 (-97.12, 53.595) -> (-107.12, 53.595)
  line L12 (-97.12, 67.595) -> (-97.12, 53.595)
  circle C1 centre (126.5, 88.1) radius 2
  circle C2 centre (135.5, 88.1) radius 2
  circle C3 centre (135.5, 13.9214) radius 2
  circle C4 centre (126.5, 13.9214) radius 2
  point P13 (-97.12, 67.595)
  point P14 (-97.12, 67.595)
  point P15 (-107.12, 67.595)
  point P17 (-97.12, 53.595)
  horizontal L9
  vertical L10
  horizontal L11
  vertical L12
  coincident P13 P14
  dimension "d214" distance P14 P15 = 10
  dimension "d215" distance P14 P17 = 14 (= "( FrameOffsetFromCase + 5 mm ) * 2")
extrude "Extrude34" cut sketch "Sketch28" profile of L7 L9 L10 L11 L12 against normal blind 10
mirror "Mirror5" mirrorStitchTolerance 0.1
sketch "Sketch29" plane through (0, 0, 0) normal (0, -1, 0) x axis (1, 0, 0)
  line L1 (95.12, 65.595) -> (95.12, -65.595)
  line L2 (-95.12, 65.595) -> (95.12, 65.595)
  line L3 (-95.12, -65.595) -> (-95.12, 65.595)
  line L4 (95.12, -65.595) -> (-95.12, -65.595)
  line L5 (-94.12, 64.595) -> (-86.12, 64.595)
  line L6 (-94.12, 56.595) -> (-94.12, 64.595)
  line L7 (-86.12, 56.595) -> (-94.12, 56.595)
  line L8 (-86.12, 64.595) -> (-86.12, 56.595)
  line L9 (-94.12, 56.595) -> (-86.12, 64.595)
  line L10 (-86.12, 56.595) -> (-94.12, 64.595)
  circle C1 centre (-90.12, 60.595) radius 2.25
  point P11 (-90.12, 60.595)
  point P2 (-90.12, 60.595)
  point P9 (-94.12, 56.595)
  point P10 (-86.12, 56.595)
  point P8 (-94.12, 64.595)
  horizontal L5
  perpendicular L5 L6
  parallel L5 L7
  parallel L6 L8
  coincident L9 P11
  coincident L10 P11
  coincident P2 P11
  dimension "d220" distance P9 P10 = 8
  dimension "d221" distance P8 P9 = 8
extrude "Extrude35" add sketch "Sketch29" profile of C1 L5 L6 L7 L8 along normal blind 3
work_plane "WorkPlane5"
mirror "Mirror6" mirrorStitchTolerance 0.1
extrude "Extrude36" add of existing geometry to an object
sketch "Sketch30" plane through (-95.12, 0, 0) normal (-1, 0, 0) x axis (0, -1, 0)
  line L1 (0, 65.595) -> (0, 64.595)
  line L2 (-9.525, 65.595) -> (0, 65.595)
  line L3 (-9.525, 64.595) -> (-9.525, 65.595)
  line L4 (-12.525, 64.595) -> (-9.525, 64.595)
  line L5 (-12.525, 56.595) -> (-12.525, 64.595)
  line L6 (-9.525, 56.595) -> (-12.525, 56.595)
  line L7 (-9.525, -65.595) -> (-9.525, 56.595)
  line L8 (0, -65.595) -> (-9.525, -65.595)
  line L9 (0, 56.595) -> (0, -65.595)
  line L10 (3, 56.595) -> (0, 56.595)
  line L11 (3, 64.595) -> (3, 56.595)
  line L12 (0, 64.595) -> (3, 64.595)
  line L13 (0, 64.595) -> (-9.525, 64.595)
  line L14 (-9.525, 56.595) -> (0, 56.595)
  point P5 (-9.525, 64.595)
  point P14 (-9.525, 64.595)
  point P2 (0, 64.595)
  point P15 (0, 64.595)
  point P11 (0, 56.595)
  point P16 (0, 56.595)
  point P8 (-9.525, 56.595)
  point P17 (-9.525, 56.595)
  coincident P5 P14
  coincident P2 P15
  coincident P11 P16
  coincident P8 P17
extrude "Extrude37" add sketch "Sketch30" profile of L4 L5 L6 L10 L11 L12 L13 L14 along normal blind 3
sketch "Sketch31" plane through (0, 0, 0) normal (0, -1, 0) x axis (1, 0, 0)
  line L1 (97.12, 53.595) -> (107.12, 53.595)
  line L2 (97.12, -67.595) -> (97.12, 53.595)
  line L3 (-97.12, -67.595) -> (97.12, -67.595)
  line L4 (-97.12, 53.595) -> (-97.12, -67.595)
  line L5 (-107.12, 53.595) -> (-97.12, 53.595)
  line L6 (-107.12, 67.595) -> (-107.12, 53.595)
  line L7 (107.12, 67.595) -> (-107.12, 67.595)
  line L8 (107.12, 53.595) -> (107.12, 67.595)
  line L9 (-147.12, -117.595) -> (-147.12, 137.595)
  line L10 (147.12, -117.595) -> (-147.12, -117.595)
  line L11 (147.12, 137.595) -> (147.12, -117.595)
  line L12 (-147.12, 137.595) -> (147.12, 137.595)
  line L13 (-107.12, 64.595) -> (-98.12, 64.595)
  line L14 (-102.62, 71.595) -> (-102.62, 64.595)
  circle C1 centre (126.5, 13.9214) radius 2
  circle C2 centre (135.5, 13.9214) radius 2
  circle C3 centre (135.5, 88.1) radius 2
  circle C4 centre (126.5, 88.1) radius 2
  circle C5 centre (-102.62, 71.595) radius 2
  point P18 (-98.12, 64.595)
  point P19 (-98.12, 64.595)
  point P20 (-107.12, 64.595)
  point P21 (-102.62, 64.595)
  point P22 (-102.62, 71.595)
  point P23 (-102.62, 71.595)
  coincident P18 P19
  coincident L6 P20
  perpendicular L6 L13
  midpoint L13 P21
  perpendicular L13 L14
  coincident P22 P23
  dimension "d230" diameter C5 = 4
  dimension "d231" distance L7 P23 = 4
extrude "Extrude38" cut sketch "Sketch31" profile of C5 against normal blind 10
extrude "Extrude39" cut of existing geometry blind -6.35 (= "-3.175 mm * 2")
move "Move4"
sketch "Sketch32" plane through (0, 3.175, 0) normal (0, -1, 0) x axis (1, 0, 0)
  line L1 (97.12, 53.595) -> (107.12, 53.595)
  line L2 (97.12, -67.595) -> (97.12, 53.595)
  line L3 (-97.12, -67.595) -> (97.12, -67.595)
  line L4 (-97.12, 53.595) -> (-97.12, -67.595)
  line L5 (-107.12, 53.595) -> (-97.12, 53.595)
  line L6 (-107.12, 67.595) -> (-107.12, 53.595)
  line L7 (107.12, 67.595) -> (-107.12, 67.595)
  line L8 (107.12, 53.595) -> (107.12, 67.595)
  line L9 (-147.12, -117.595) -> (-147.12, 137.595)
  line L10 (147.12, -117.595) -> (-147.12, -117.595)
  line L11 (147.12, 137.595) -> (147.12, -117.595)
  line L12 (-147.12, 137.595) -> (147.12, 137.595)
  line L13 (-106.62, 75.595) -> (-98.62, 75.595)
  line L14 (-106.62, 67.595) -> (-106.62, 75.595)
  line L15 (-98.62, 67.595) -> (-106.62, 67.595)
  line L16 (-98.62, 75.595) -> (-98.62, 67.595)
  line L17 (-106.62, 67.595) -> (-98.62, 75.595)
  line L18 (-98.62, 67.595) -> (-106.62, 75.595)
  circle C1 centre (-102.62, 71.595) radius 2
  circle C2 centre (126.5, 13.9214) radius 2
  circle C3 centre (135.5, 13.9214) radius 2
  circle C4 centre (135.5, 88.1) radius 2
  circle C5 centre (126.5, 88.1) radius 2
  point P23 (-102.62, 71.595)
  point P2 (-102.62, 71.595)
  point P21 (-106.62, 67.595)
  point P22 (-98.62, 67.595)
  point P20 (-106.62, 75.595)
  horizontal L13
  perpendicular L13 L14
  parallel L13 L15
  parallel L14 L16
  coincident L17 P23
  coincident L18 P23
  coincident P2 P23
  dimension "d236" distance P21 P22 = 8
  dimension "d237" distance P20 P21 = 8
extrude "Extrude40" add sketch "Sketch32" profile of C1 L7 L13 L14 L15 L16 along normal blind 3
mirror "Mirror7" mirrorStitchTolerance 0.1
sketch "Sketch33" plane through (0, 0, 67.595) normal (0, 0, -1) x axis (1, 0, 0)
  line L1 (-98.62, -3.175) -> (107.12, -3.175)
  line L2 (-98.62, -0.175) -> (-98.62, -3.175)
  line L3 (-106.62, -0.175) -> (-98.62, -0.175)
  line L4 (-106.62, -3.175) -> (-106.62, -0.175)
  line L5 (-107.12, -3.175) -> (-106.62, -3.175)
  line L6 (-107.12, -6.35) -> (-107.12, -3.175)
  line L7 (-106.62, -6.35) -> (-107.12, -6.35)
  line L8 (-106.62, -9.35) -> (-106.62, -6.35)
  line L9 (-98.62, -9.35) -> (-106.62, -9.35)
  line L10 (-98.62, -6.35) -> (-98.62, -9.35)
  line L11 (107.12, -6.35) -> (-98.62, -6.35)
  line L12 (107.12, -3.175) -> (107.12, -6.35)
  line L13 (-98.62, -6.35) -> (-98.62, -3.175)
  line L14 (-106.62, -6.35) -> (-106.62, -3.175)
  point P3 (-98.62, -3.175)
  point P14 (-98.62, -3.175)
  point P12 (-98.62, -6.35)
  point P15 (-98.62, -6.35)
  point P6 (-106.62, -3.175)
  point P16 (-106.62, -3.175)
  point P9 (-106.62, -6.35)
  point P17 (-106.62, -6.35)
  coincident P3 P14
  coincident P12 P15
  coincident P6 P16
  coincident P9 P17
extrude "Extrude41" add sketch "Sketch33" profile of L2 L3 L4 L8 L9 L10 L13 L14 along normal blind 3
sketch "Sketch34" plane through (-98.12, 0, 0) normal (-1, 0, 0) x axis (0, -1, 0)
  line L1 (3, 64.595) -> (3, 56.595)
  line L2 (-12.525, 64.595) -> (3, 64.595)
  line L3 (-12.525, 56.595) -> (-12.525, 64.595)
  line L4 (3, 56.595) -> (-12.525, 56.595)
  line L5 (3, 60.595) -> (-12.525, 60.595)
  line L6 (-4.7625, 58.6206) -> (-4.7625, 60.595)
  circle C1 centre (-4.7625, 60.595) radius 2.5
  circle C2 centre (-4.7625, 60.595) radius 3.5
  point P6 (-12.525, 60.595)
  point P7 (3, 60.595)
  point P8 (-4.7625, 60.595)
  point P10 (-4.7625, 60.595)
  coincident L3 P6
  coincident L1 P7
  perpendicular L1 L5
  midpoint L5 P8
  perpendicular L5 L6
  midpoint L1 P7
  coincident P8 P10
  dimension "d244" diameter C1 = 5
  dimension "d245" = 1
extrude "Extrude42" new body sketch "Sketch34" profile of C1 C2 to an object
extrude "Extrude43" cut of existing geometry to an object
extrude "Extrude44" cut of existing geometry blind -2
extrude "Extrude45" cut of existing geometry blind -2
sketch "Sketch35" plane through (0, 0, 64.595) normal (0, 0, -1) x axis (1, 0, 0)
  line L1 (-98.62, -0.175) -> (-98.62, -9.35)
  line L2 (-106.62, -0.175) -> (-98.62, -0.175)
  line L3 (-106.62, -9.35) -> (-106.62, -0.175)
  line L4 (-98.62, -9.35) -> (-106.62, -9.35)
  line L5 (-104.62, -1.2625) -> (-104.62, -8.2625)
  line L6 (-100.62, -8.2625) -> (-100.62, -1.2625)
  line L7 (-100.62, -1.2625) -> (-104.62, -1.2625)
  line L8 (-104.62, -8.2625) -> (-100.62, -8.2625)
  point P7 (-104.62, -1.2625)
  point P10 (-104.62, -1.2625)
  point P8 (-100.62, -1.2625)
  point P11 (-100.62, -1.2625)
  point P9 (-100.62, -8.2625)
  point P12 (-100.62, -8.2625)
  point P6 (-104.62, -8.2625)
  point P13 (-104.62, -8.2625)
  coincident P7 P10
  coincident P8 P11
  coincident P9 P12
  coincident P6 P13
extrude "Extrude46" add sketch "Sketch35" profile of L5 L6 L7 L8 to an object
extrude "Extrude47" new body sketch "Sketch34" profile of C1 along normal blind 7.5 bodies "CaseHinge1"
combine "Combine7"
offset_faces "OffsetFaces1"
fillet "Fillet12" radius 2
sketch "Sketch36" plane through (-105.62, 0, 0) normal (-1, 0, 0) x axis (0, -1, 0)
  circle C1 centre (-4.7625, 60.595) radius 2.3
  circle C2 centre (-4.7625, 60.595) radius 3
  concentric C1 C2
  dimension "d262" diameter C2 = 6
extrude "Extrude48" add sketch "Sketch36" along normal blind 0.75
fillet "Fillet13" radius 1
fillet "Fillet14" radius 1
sketch "Sketch37" plane through (0, 3.175, 0) normal (0, -1, 0) x axis (1, 0, 0)
  line L1 (-147.12, -117.595) -> (-147.12, 137.595)
  line L2 (147.12, -117.595) -> (-147.12, -117.595)
  line L3 (147.12, 137.595) -> (147.12, -117.595)
  line L4 (-147.12, 137.595) -> (147.12, 137.595)
  line L5 (-106.62, 75.595) -> (-106.62, 67.595)
  line L6 (-98.62, 75.595) -> (-106.62, 75.595)
  line L7 (-98.62, 67.595) -> (-98.62, 75.595)
  line L8 (107.12, 67.595) -> (-98.62, 67.595)
  line L9 (107.12, 53.595) -> (107.12, 67.595)
  line L10 (97.12, 53.595) -> (107.12, 53.595)
  line L11 (97.12, -67.595) -> (97.12, 53.595)
  line L12 (-97.12, -67.595) -> (97.12, -67.595)
  line L13 (-97.12, 53.595) -> (-97.12, -67.595)
  line L14 (-107.12, 53.595) -> (-97.12, 53.595)
  line L15 (-107.12, 67.595) -> (-107.12, 53.595)
  line L16 (-106.62, 67.595) -> (-107.12, 67.595)
  line L17 (-109.1388, 67.595) -> (-94.8981, 67.595)
  line L18 (-109.1388, 77.6179) -> (-109.1388, 67.595)
  line L19 (-94.8981, 77.6179) -> (-109.1388, 77.6179)
  line L20 (-94.8981, 67.595) -> (-94.8981, 77.6179)
  circle C1 centre (126.5, 88.1) radius 2
  circle C2 centre (135.5, 88.1) radius 2
  circle C3 centre (135.5, 13.9214) radius 2
  circle C4 centre (126.5, 13.9214) radius 2
  point P22 (-94.8981, 67.595)
  horizontal L17
  vertical L18
  horizontal L19
  vertical L20
  coincident L8 P22
extrude "Extrude49" new body sketch "Sketch37" profile of L5 L6 L7 L8 L16 L17 L18 L19 L20 to an object bodies "Frame"
combine "Combine8" bodies "Frame (1)"
combine "Combine9" bodies "Frame (1)"
component_from_bodies "Body->Comp3"
sketch "Sketch38" plane through (0, 3.175, 0) normal (0, -1, 0) x axis (1, 0, 0)
  line L1 (-147.12, -117.595) -> (-147.12, 137.595)
  line L2 (147.12, -117.595) -> (-147.12, -117.595)
  line L3 (147.12, 137.595) -> (147.12, -117.595)
  line L4 (-147.12, 137.595) -> (147.12, 137.595)
  line L5 (107.12, 67.595) -> (-107.12, 67.595)
  line L6 (107.12, 53.595) -> (107.12, 67.595)
  line L7 (97.12, 53.595) -> (107.12, 53.595)
  line L8 (97.12, -67.595) -> (97.12, 53.595)
  line L9 (-97.12, -67.595) -> (97.12, -67.595)
  line L10 (-97.12, 53.595) -> (-97.12, -67.595)
  line L11 (-107.12, 53.595) -> (-97.12, 53.595)
  line L12 (-107.12, 67.595) -> (-107.12, 53.595)
  circle C1 centre (126.5, 88.1) radius 2
  circle C2 centre (135.5, 88.1) radius 2
  circle C3 centre (135.5, 13.9214) radius 2
  circle C4 centre (126.5, 13.9214) radius 2
  circle C5 centre (-102.62, 71.595) radius 2
extrude "Extrude50" cut sketch "Sketch38" profile of C5 against normal blind 10
sketch "Sketch39" plane through (0, 0, 0) normal (0, -1, 0) x axis (1, 0, 0)
  line L1 (-86.12, 64.595) -> (-95.12, 64.595)
  line L2 (-86.12, 56.595) -> (-86.12, 64.595)
  line L3 (-95.12, 56.595) -> (-86.12, 56.595)
  line L4 (-95.12, -65.595) -> (-95.12, 56.595)
  line L5 (95.12, -65.595) -> (-95.12, -65.595)
  line L6 (95.12, 65.595) -> (95.12, -65.595)
  line L7 (-95.12, 65.595) -> (95.12, 65.595)
  line L8 (-95.12, 64.595) -> (-95.12, 65.595)
  line L9 (-83, 65.595) -> (-95.12, 65.595)
  line L10 (-83, 54) -> (-83, 65.595)
  line L11 (-95.12, 54) -> (-83, 54)
  line L12 (-95.12, 65.595) -> (-95.12, 54)
  point P9 (-95.12, 65.595)
  point P10 (-95.12, 65.595)
  horizontal L9
  vertical L10
  horizontal L11
  vertical L12
  coincident P9 P10
extrude "Extrude51" new body sketch "Sketch39" profile of L1 L2 L3 L4 L7 L8 L9 L10 L11 L12 against normal blind 9.525
combine "Combine10" bodies "Case"
combine "Combine12"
